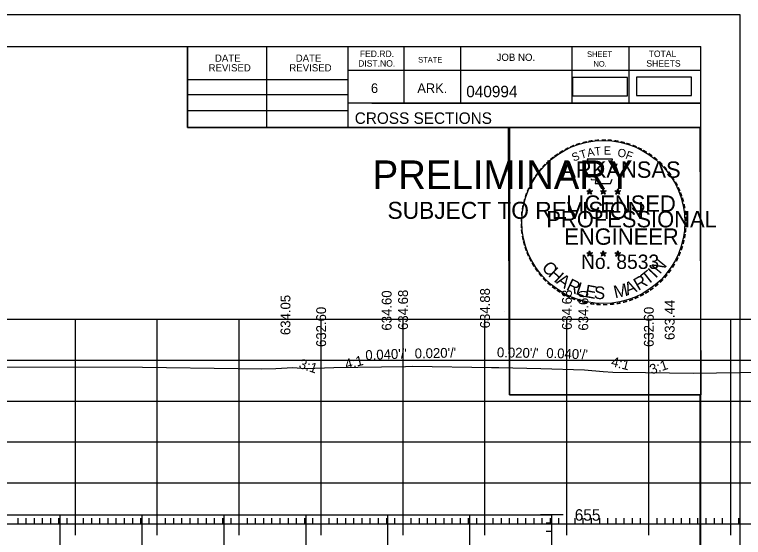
# Model space of a CAD drawing. Extents: x 1381471 to 1382703, y 370300 to 371487.
# Drawn here: x 1382079.2 to 1382168.2, y 371123.8 to 371187.6 of the extents above; entities that cross this region are included whole.
import ezdxf

# ---------------------------------------------------------------- set-up
doc = ezdxf.new("R2010")
doc.units = 0
for name, color, linetype in [('Level 22', 7, 'Continuous'), ('Level 26', 7, 'Continuous'), ('Level 4', 7, 'Continuous'), ('Level 45', 7, 'Continuous'), ('Level 5', 7, 'Continuous'), ('Level 6', 7, 'Continuous'), ('Level 8', 7, 'Continuous'), ('Level 9', 7, 'Continuous')]:
    doc.layers.add(name, color=color, linetype=linetype)

msp = doc.modelspace()

# ---------------------------------------------------------------- linework, layer by layer
at = {"layer": 'Level 22'}
for p, q in [((1381864.772, 371126.544), (1382144.772, 371126.544)), ((1382084.772, 371091.544), (1382084.772, 371126.544)), ((1382094.772, 371091.544), (1382094.772, 371126.544)), ((1382104.772, 371091.544), (1382104.772, 371126.544)), ((1382114.772, 371091.544), (1382114.772, 371126.544)), ((1382124.772, 371091.544), (1382124.772, 371126.544)), ((1382134.772, 371091.544), (1382134.772, 371126.544)), ((1382144.772, 371091.544), (1382144.772, 371126.544))]:
    msp.add_line(p, q, dxfattribs=at)
at = {"layer": 'Level 26'}
for p, q in [((1381834.371, 371187.641), (1382167.705, 371187.641)), ((1382138.986, 371151.411), (1382138.986, 371151.411))]:
    msp.add_line(p, q, dxfattribs=at)
for points in [[(1381834.365, 371187.641), (1382167.705, 371187.641), (1382167.705, 370974.304), (1381834.365, 370974.304)], [(1382080.692, 371183.746), (1382100.312, 371183.746), (1382100.312, 371173.866), (1382116.424, 371173.866), (1382139.624, 371173.866), (1382139.624, 371141.196), (1382162.831, 371141.196), (1382162.952, 370978.286), (1381846.772, 370978.286), (1381846.772, 371183.746)], [(1382139.484, 371173.866), (1382162.831, 371173.866), (1382162.972, 371141.196), (1382139.624, 371141.196)]]:
    msp.add_lwpolyline(points, close=True, dxfattribs=at)
msp.add_circle((1382151.064, 371162.306), 9.952, dxfattribs=at)
at = {"layer": 'Level 4'}
for p, q in [((1382146.172, 371126.544), (1382143.372, 371126.544)), ((1382144.772, 371091.544), (1382144.772, 371126.544)), ((1382144.772, 371125.544), (1382144.072, 371125.544)), ((1382144.772, 371124.544), (1382144.072, 371124.544))]:
    msp.add_line(p, q, dxfattribs=at)
at = {"layer": 'Level 45'}
for p, q in [((1381996.613, 371150.458), (1382276.613, 371150.458)), ((1382086.613, 371125.458), (1382086.613, 371150.458)), ((1382096.613, 371125.458), (1382096.613, 371150.458)), ((1382106.613, 371125.458), (1382106.613, 371150.458)), ((1382116.613, 371125.458), (1382116.613, 371150.458)), ((1382126.613, 371125.458), (1382126.613, 371150.458)), ((1382136.613, 371125.458), (1382136.613, 371150.458)), ((1382146.613, 371125.458), (1382146.613, 371150.458)), ((1382156.613, 371125.458), (1382156.613, 371150.458)), ((1382166.613, 371125.458), (1382166.613, 371150.458)), ((1381996.613, 371145.458), (1382276.613, 371145.458)), ((1381996.613, 371140.458), (1382276.613, 371140.458)), ((1381996.613, 371135.458), (1382276.613, 371135.458)), ((1381996.613, 371130.458), (1382276.613, 371130.458)), ((1382086.613, 371124.058), (1382086.613, 371126.858)), ((1382096.613, 371124.058), (1382096.613, 371126.858)), ((1382106.613, 371124.058), (1382106.613, 371126.858)), ((1382116.613, 371124.058), (1382116.613, 371126.858)), ((1382126.613, 371124.058), (1382126.613, 371126.858)), ((1382136.613, 371124.058), (1382136.613, 371126.858)), ((1382146.613, 371124.058), (1382146.613, 371126.858)), ((1382156.613, 371124.058), (1382156.613, 371126.858)), ((1382166.613, 371124.058), (1382166.613, 371126.858)), ((1381996.613, 371125.458), (1382276.613, 371125.458)), ((1381996.613, 371125.458), (1382276.613, 371125.458)), ((1382079.613, 371125.458), (1382079.613, 371126.158)), ((1382080.613, 371125.458), (1382080.613, 371126.158)), ((1382081.613, 371125.458), (1382081.613, 371126.158)), ((1382082.613, 371125.458), (1382082.613, 371126.158)), ((1382083.613, 371125.458), (1382083.613, 371126.158)), ((1382084.613, 371125.458), (1382084.613, 371126.158)), ((1382085.613, 371125.458), (1382085.613, 371126.158)), ((1382087.613, 371125.458), (1382087.613, 371126.158)), ((1382088.613, 371125.458), (1382088.613, 371126.158)), ((1382089.613, 371125.458), (1382089.613, 371126.158)), ((1382090.613, 371125.458), (1382090.613, 371126.158)), ((1382091.613, 371125.458), (1382091.613, 371126.158)), ((1382092.613, 371125.458), (1382092.613, 371126.158)), ((1382093.613, 371125.458), (1382093.613, 371126.158)), ((1382094.613, 371125.458), (1382094.613, 371126.158)), ((1382095.613, 371125.458), (1382095.613, 371126.158)), ((1382097.613, 371125.458), (1382097.613, 371126.158)), ((1382098.613, 371125.458), (1382098.613, 371126.158)), ((1382099.613, 371125.458), (1382099.613, 371126.158)), ((1382100.613, 371125.458), (1382100.613, 371126.158)), ((1382101.613, 371125.458), (1382101.613, 371126.158)), ((1382102.613, 371125.458), (1382102.613, 371126.158)), ((1382103.613, 371125.458), (1382103.613, 371126.158)), ((1382104.613, 371125.458), (1382104.613, 371126.158)), ((1382105.613, 371125.458), (1382105.613, 371126.158)), ((1382107.613, 371125.458), (1382107.613, 371126.158)), ((1382108.613, 371125.458), (1382108.613, 371126.158)), ((1382109.613, 371125.458), (1382109.613, 371126.158)), ((1382110.613, 371125.458), (1382110.613, 371126.158)), ((1382111.613, 371125.458), (1382111.613, 371126.158)), ((1382112.613, 371125.458), (1382112.613, 371126.158)), ((1382113.613, 371125.458), (1382113.613, 371126.158)), ((1382114.613, 371125.458), (1382114.613, 371126.158)), ((1382115.613, 371125.458), (1382115.613, 371126.158)), ((1382117.613, 371125.458), (1382117.613, 371126.158)), ((1382118.613, 371125.458), (1382118.613, 371126.158)), ((1382119.613, 371125.458), (1382119.613, 371126.158)), ((1382120.613, 371125.458), (1382120.613, 371126.158)), ((1382121.613, 371125.458), (1382121.613, 371126.158)), ((1382122.613, 371125.458), (1382122.613, 371126.158)), ((1382123.613, 371125.458), (1382123.613, 371126.158)), ((1382124.613, 371125.458), (1382124.613, 371126.158)), ((1382125.613, 371125.458), (1382125.613, 371126.158)), ((1382127.613, 371125.458), (1382127.613, 371126.158)), ((1382128.613, 371125.458), (1382128.613, 371126.158)), ((1382129.613, 371125.458), (1382129.613, 371126.158)), ((1382130.613, 371125.458), (1382130.613, 371126.158)), ((1382131.613, 371125.458), (1382131.613, 371126.158)), ((1382132.613, 371125.458), (1382132.613, 371126.158)), ((1382133.613, 371125.458), (1382133.613, 371126.158)), ((1382134.613, 371125.458), (1382134.613, 371126.158)), ((1382135.613, 371125.458), (1382135.613, 371126.158)), ((1382137.613, 371125.458), (1382137.613, 371126.158)), ((1382138.613, 371125.458), (1382138.613, 371126.158)), ((1382139.613, 371125.458), (1382139.613, 371126.158)), ((1382140.613, 371125.458), (1382140.613, 371126.158)), ((1382141.613, 371125.458), (1382141.613, 371126.158)), ((1382142.613, 371125.458), (1382142.613, 371126.158)), ((1382143.613, 371125.458), (1382143.613, 371126.158)), ((1382144.613, 371125.458), (1382144.613, 371126.158)), ((1382145.613, 371125.458), (1382145.613, 371126.158)), ((1382147.613, 371125.458), (1382147.613, 371126.158)), ((1382148.613, 371125.458), (1382148.613, 371126.158)), ((1382149.613, 371125.458), (1382149.613, 371126.158)), ((1382150.613, 371125.458), (1382150.613, 371126.158)), ((1382151.613, 371125.458), (1382151.613, 371126.158)), ((1382152.613, 371125.458), (1382152.613, 371126.158)), ((1382153.613, 371125.458), (1382153.613, 371126.158)), ((1382154.613, 371125.458), (1382154.613, 371126.158)), ((1382155.613, 371125.458), (1382155.613, 371126.158)), ((1382157.613, 371125.458), (1382157.613, 371126.158)), ((1382158.613, 371125.458), (1382158.613, 371126.158)), ((1382159.613, 371125.458), (1382159.613, 371126.158)), ((1382160.613, 371125.458), (1382160.613, 371126.158)), ((1382161.613, 371125.458), (1382161.613, 371126.158)), ((1382162.613, 371125.458), (1382162.613, 371126.158)), ((1382163.613, 371125.458), (1382163.613, 371126.158)), ((1382164.613, 371125.458), (1382164.613, 371126.158)), ((1382165.613, 371125.458), (1382165.613, 371126.158)), ((1382167.613, 371125.458), (1382167.613, 371126.158))]:
    msp.add_line(p, q, dxfattribs=at)
msp.add_lwpolyline([(1382075.859, 371144.641), (1382094.82, 371144.584), (1382097.722, 371144.529), (1382109.377, 371144.395), (1382111.088, 371144.427), (1382113.157, 371144.567), (1382114.7, 371144.426), (1382118.153, 371144.529), (1382126.912, 371144.655), (1382127.752, 371144.716), (1382137.401, 371144.565), (1382138.304, 371144.552), (1382143.434, 371144.41), (1382148.756, 371144.259), (1382151.033, 371144.049), (1382152.228, 371143.96), (1382156.21, 371143.935), (1382162.082, 371143.871), (1382170.525, 371143.981)], dxfattribs=at)
at = {"layer": 'Level 6'}
for p, q in [((1381846.772, 371183.746), (1382162.952, 371183.746)), ((1382100.312, 371173.866), (1382100.312, 371183.746)), ((1382109.992, 371173.866), (1382109.992, 371183.746)), ((1382119.852, 371183.746), (1382119.852, 371173.866)), ((1382126.692, 371183.746), (1382126.692, 371176.806)), ((1382133.632, 371183.746), (1382133.632, 371176.806)), ((1382147.212, 371183.746), (1382147.212, 371176.806)), ((1382154.152, 371183.746), (1382154.152, 371176.806)), ((1382162.952, 370978.286), (1382162.952, 371183.746)), ((1382162.952, 371180.806), (1382119.852, 371180.806)), ((1382162.952, 371180.826), (1382162.952, 371180.826)), ((1382100.312, 371179.726), (1382119.852, 371179.726)), ((1382100.312, 371177.866), (1382119.852, 371177.866)), ((1382162.952, 371176.806), (1382119.852, 371176.806)), ((1382122.812, 371176.806), (1382162.952, 371176.806)), ((1382100.312, 371175.926), (1382119.852, 371175.926)), ((1382162.952, 371173.866), (1382100.312, 371173.866))]:
    msp.add_line(p, q, dxfattribs=at)
for points in [[(1382147.299, 371177.703), (1382154.01, 371177.703), (1382154.01, 371179.94), (1382147.299, 371179.94)], [(1382155.106, 371177.776), (1382161.817, 371177.776), (1382161.817, 371180.013), (1382155.106, 371180.013)]]:
    msp.add_lwpolyline(points, close=True, dxfattribs=at)
at = {"layer": 'Level 8'}
for p, q in [((1382149.386, 371166.376), (1382149.345, 371166.124)), ((1382149.386, 371166.011), (1382149.386, 371166.376)), ((1382149.386, 371166.376), (1382149.435, 371166.126)), ((1382151.056, 371166.376), (1382151.015, 371166.124)), ((1382151.056, 371166.011), (1382151.056, 371166.376)), ((1382151.056, 371166.376), (1382151.105, 371166.126)), ((1382152.82, 371166.364), (1382152.779, 371166.112)), ((1382152.82, 371165.999), (1382152.82, 371166.364)), ((1382152.82, 371166.364), (1382152.869, 371166.114)), ((1382149.037, 371166.122), (1382149.386, 371166.011)), ((1382149.037, 371166.122), (1382149.29, 371166.077)), ((1382149.037, 371166.122), (1382149.274, 371166)), ((1382149.17, 371165.714), (1382149.386, 371166.011)), ((1382149.17, 371165.714), (1382149.296, 371165.958)), ((1382149.17, 371165.714), (1382149.384, 371165.931)), ((1382149.599, 371165.714), (1382149.384, 371165.928)), ((1382149.733, 371166.122), (1382149.386, 371166.011)), ((1382149.599, 371165.714), (1382149.386, 371166.011)), ((1382149.733, 371166.122), (1382149.447, 371166.073)), ((1382149.599, 371165.714), (1382149.462, 371166.005)), ((1382149.733, 371166.122), (1382149.529, 371166.02)), ((1382150.707, 371166.122), (1382151.056, 371166.011)), ((1382150.707, 371166.122), (1382150.96, 371166.077)), ((1382150.707, 371166.122), (1382150.944, 371166)), ((1382150.84, 371165.714), (1382151.056, 371166.011)), ((1382150.84, 371165.714), (1382150.966, 371165.958)), ((1382150.84, 371165.714), (1382151.054, 371165.931)), ((1382151.269, 371165.714), (1382151.054, 371165.928)), ((1382151.403, 371166.122), (1382151.056, 371166.011)), ((1382151.269, 371165.714), (1382151.056, 371166.011)), ((1382151.403, 371166.122), (1382151.117, 371166.073)), ((1382151.269, 371165.714), (1382151.132, 371166.005)), ((1382151.403, 371166.122), (1382151.199, 371166.02)), ((1382152.471, 371166.11), (1382152.82, 371165.999)), ((1382152.471, 371166.11), (1382152.724, 371166.065)), ((1382152.471, 371166.11), (1382152.708, 371165.988)), ((1382152.604, 371165.702), (1382152.82, 371165.999)), ((1382152.604, 371165.702), (1382152.73, 371165.946)), ((1382152.604, 371165.702), (1382152.818, 371165.919)), ((1382153.033, 371165.702), (1382152.818, 371165.916)), ((1382153.167, 371166.11), (1382152.82, 371165.999)), ((1382153.033, 371165.702), (1382152.82, 371165.999)), ((1382153.167, 371166.11), (1382152.881, 371166.061)), ((1382153.033, 371165.702), (1382152.896, 371165.993)), ((1382153.167, 371166.11), (1382152.963, 371166.008)), ((1382149.033, 371158.549), (1382149.382, 371158.438)), ((1382149.033, 371158.549), (1382149.286, 371158.504)), ((1382149.033, 371158.549), (1382149.27, 371158.427)), ((1382149.166, 371158.141), (1382149.382, 371158.438)), ((1382149.166, 371158.141), (1382149.292, 371158.385)), ((1382149.166, 371158.141), (1382149.38, 371158.358)), ((1382149.382, 371158.803), (1382149.341, 371158.551)), ((1382149.595, 371158.141), (1382149.38, 371158.355)), ((1382149.382, 371158.438), (1382149.382, 371158.803)), ((1382149.382, 371158.803), (1382149.431, 371158.553)), ((1382149.729, 371158.549), (1382149.382, 371158.438)), ((1382149.595, 371158.141), (1382149.382, 371158.438)), ((1382149.729, 371158.549), (1382149.443, 371158.5)), ((1382149.595, 371158.141), (1382149.458, 371158.432)), ((1382149.729, 371158.549), (1382149.525, 371158.447)), ((1382150.702, 371158.549), (1382151.051, 371158.438)), ((1382150.702, 371158.549), (1382150.955, 371158.504)), ((1382150.702, 371158.549), (1382150.939, 371158.427)), ((1382150.835, 371158.141), (1382151.051, 371158.438)), ((1382150.835, 371158.141), (1382150.961, 371158.385)), ((1382150.835, 371158.141), (1382151.049, 371158.358)), ((1382151.051, 371158.803), (1382151.01, 371158.551)), ((1382151.264, 371158.141), (1382151.049, 371158.355)), ((1382151.051, 371158.438), (1382151.051, 371158.803)), ((1382151.051, 371158.803), (1382151.1, 371158.553)), ((1382151.398, 371158.549), (1382151.051, 371158.438)), ((1382151.264, 371158.141), (1382151.051, 371158.438)), ((1382151.398, 371158.549), (1382151.112, 371158.5)), ((1382151.264, 371158.141), (1382151.127, 371158.432)), ((1382151.398, 371158.549), (1382151.194, 371158.447)), ((1382152.469, 371158.539), (1382152.818, 371158.428)), ((1382152.469, 371158.539), (1382152.722, 371158.494)), ((1382152.469, 371158.539), (1382152.706, 371158.417)), ((1382152.602, 371158.131), (1382152.818, 371158.428)), ((1382152.602, 371158.131), (1382152.728, 371158.375)), ((1382152.602, 371158.131), (1382152.816, 371158.348)), ((1382152.818, 371158.793), (1382152.777, 371158.541)), ((1382153.031, 371158.131), (1382152.816, 371158.345)), ((1382152.818, 371158.428), (1382152.818, 371158.793)), ((1382152.818, 371158.793), (1382152.867, 371158.543)), ((1382153.165, 371158.539), (1382152.818, 371158.428)), ((1382153.031, 371158.131), (1382152.818, 371158.428)), ((1382153.165, 371158.539), (1382152.879, 371158.49)), ((1382153.031, 371158.131), (1382152.894, 371158.422)), ((1382153.165, 371158.539), (1382152.961, 371158.437))]:
    msp.add_line(p, q, dxfattribs=at)
for points in [[(1382149.078, 371170), (1382149.347, 371169.173)], [(1382152.589, 371169.078), (1382152.731, 371169.362), (1382152.046, 371169.338), (1382152.194, 371170), (1382149.078, 371170)], [(1382149.57, 371167.577), (1382149.57, 371167.49), (1382150.133, 371167.471), (1382150.079, 371166.998), (1382151.949, 371166.998), (1382152.15, 371167.534)], [(1382149.386, 371166.376), (1382149.599, 371165.714), (1382149.037, 371166.122), (1382149.733, 371166.122), (1382149.17, 371165.714), (1382149.386, 371166.376)], [(1382151.056, 371166.376), (1382151.269, 371165.714), (1382150.707, 371166.122), (1382151.403, 371166.122), (1382150.84, 371165.714), (1382151.056, 371166.376)], [(1382152.82, 371166.364), (1382153.033, 371165.702), (1382152.471, 371166.11), (1382153.167, 371166.11), (1382152.604, 371165.702), (1382152.82, 371166.364)], [(1382149.382, 371158.803), (1382149.595, 371158.141), (1382149.033, 371158.549), (1382149.729, 371158.549), (1382149.166, 371158.141), (1382149.382, 371158.803)], [(1382151.051, 371158.803), (1382151.264, 371158.141), (1382150.702, 371158.549), (1382151.398, 371158.549), (1382150.835, 371158.141), (1382151.051, 371158.803)], [(1382152.818, 371158.793), (1382153.031, 371158.131), (1382152.469, 371158.539), (1382153.165, 371158.539), (1382152.602, 371158.131), (1382152.818, 371158.793)]]:
    msp.add_lwpolyline(points, dxfattribs=at)
for centre, radius in [((1382149.385, 371166.01), 0.172), ((1382149.385, 371166.01), 0.145), ((1382149.385, 371166.01), 0.116), ((1382149.385, 371166.01), 0.0991), ((1382149.385, 371166.01), 0.0747), ((1382149.385, 371166.01), 0.0495), ((1382149.385, 371166.01), 0.0296), ((1382151.055, 371166.01), 0.172), ((1382151.055, 371166.01), 0.145), ((1382151.055, 371166.01), 0.116), ((1382151.055, 371166.01), 0.0991), ((1382151.055, 371166.01), 0.0747), ((1382151.055, 371166.01), 0.0495), ((1382151.055, 371166.01), 0.0296), ((1382152.819, 371165.998), 0.172), ((1382152.819, 371165.998), 0.145), ((1382152.819, 371165.998), 0.116), ((1382152.819, 371165.998), 0.0991), ((1382152.819, 371165.998), 0.0747), ((1382152.819, 371165.998), 0.0495), ((1382152.819, 371165.998), 0.0296), ((1382149.381, 371158.437), 0.172), ((1382149.381, 371158.437), 0.145), ((1382149.381, 371158.437), 0.116), ((1382149.381, 371158.437), 0.0991), ((1382149.381, 371158.437), 0.0747), ((1382149.381, 371158.437), 0.0495), ((1382149.381, 371158.437), 0.0296), ((1382151.05, 371158.437), 0.172), ((1382151.05, 371158.437), 0.145), ((1382151.05, 371158.437), 0.116), ((1382151.05, 371158.437), 0.0991), ((1382151.05, 371158.437), 0.0747), ((1382151.05, 371158.437), 0.0495), ((1382151.05, 371158.437), 0.0296), ((1382152.817, 371158.427), 0.172), ((1382152.817, 371158.427), 0.145), ((1382152.817, 371158.427), 0.116), ((1382152.817, 371158.427), 0.0991), ((1382152.817, 371158.427), 0.0747), ((1382152.817, 371158.427), 0.0495), ((1382152.817, 371158.427), 0.0296)]:
    msp.add_circle(centre, radius, dxfattribs=at)

# ---------------------------------------------------------------- texts
at = {"layer": 'Level 45'}
for s, rotation, p in [('634.60', 90, (1382125.213, 371149.055)), ('634.68', 90, (1382127.213, 371149.135)), ('634.88', 90, (1382137.213, 371149.335)), ('634.68', 90, (1382147.213, 371149.135)), ('634.60', 90, (1382149.213, 371149.055)), ('634.05', 90, (1382112.861, 371148.506)), ('633.44', 90, (1382159.757, 371147.903)), ('632.60', 90, (1382117.213, 371147.055)), ('632.60', 90, (1382157.213, 371147.055)), ("0.040'/'", 2.29061, (1382122.034, 371145.452)), ("0.020'/'", 1.14576, (1382128.042, 371145.664)), ("0.020'/'", 358.85424, (1382138.062, 371145.806)), ("0.040'/'", 357.70939, (1382144.074, 371145.737)), ('4:1', 14.03624, (1382119.685, 371144.339)), ('3:1', 341.56522, (1382113.806, 371144.518)), ('4:1', 345.96376, (1382151.928, 371144.742)), ('3:1', 18.43493, (1382156.938, 371143.69))]:
    msp.add_text(s, height=1.2, rotation=rotation, dxfattribs=at).set_placement(p)
at = {"layer": 'Level 5'}
msp.add_text('655', height=1.4, dxfattribs=at).set_placement((1382147.572, 371125.844))
at = {"layer": 'Level 6'}
for s, height, p in [('FED.RD.', 0.7819, (1382121.332, 371182.466)), ('TOTAL', 0.7819, (1382156.592, 371182.466)), ('DATE', 0.8792, (1382103.65, 371181.883)), ('DATE', 0.8792, (1382113.51, 371181.883)), ('STATE', 0.684, (1382128.452, 371181.786)), ('JOB NO.', 0.8792, (1382138.032, 371181.986)), ('SHEET', 0.684, (1382149.072, 371182.466)), ('REVISED', 0.8792, (1382102.87, 371180.703)), ('REVISED', 0.8792, (1382112.73, 371180.703)), ('DIST.NO.', 0.7819, (1382121.132, 371181.286)), ('NO.', 0.684, (1382149.852, 371181.286)), ('SHEETS', 0.7819, (1382156.312, 371181.286)), ('6', 1.172, (1382122.692, 371178.066)), ('ARK.', 1.1723, (1382128.352, 371178.066)), ('040994', 1.4, (1382134.328, 371177.546)), ('CROSS SECTIONS', 1.4, (1382120.716, 371174.297))]:
    msp.add_text(s, height=height, rotation=360, dxfattribs=at).set_placement(p)
at = {"layer": 'Level 8'}
for s, height, rotation, p in [('-', 1.6, 24.30721, (1382147.192, 371170.858)), ('-', 1.6, 19.17608, (1382147.826, 371171.127)), ('-', 1.6, 13.63015, (1382148.576, 371171.368)), ('-', 1.6, 10.21935, (1382149.254, 371171.53)), ('-', 1.6, 5.89682, (1382149.983, 371171.64)), ('-', 1.6, 0.18623, (1382150.755, 371171.712)), ('-', 1.6, 357.74304, (1382151.478, 371171.699)), ('-', 1.6, 352.16172, (1382152.222, 371171.643)), ('-', 1.6, 347.20489, (1382152.941, 371171.529)), ('-', 1.6, 342.3362, (1382153.576, 371171.374)), ('-', 1.6, 337.85509, (1382154.311, 371171.151)), ('-', 1.6, 34.06357, (1382145.962, 371170.171)), ('-', 1.6, 28.79182, (1382146.559, 371170.541)), ('S', 1, 21.59401, (1382147.433, 371169.678)), ('T', 1, 16.4036, (1382148.347, 371170.009)), ('A', 1, 11.21318, (1382149.173, 371170.26)), ('T', 1, 6.02276, (1382150.022, 371170.426)), ('E', 1, 0.83234, (1382151.127, 371170.536)), ('O', 1, 350.4515, (1382152.731, 371170.326)), ('F', 1, 340.07066, (1382153.685, 371170.098)), ('-', 1.6, 334.12109, (1382154.942, 371170.88)), ('-', 1.6, 329.64089, (1382155.521, 371170.597)), ('-', 1.6, 42.96224, (1382144.475, 371168.981)), ('-', 1.6, 38.95066, (1382144.908, 371169.398)), ('-', 1.6, 36.23174, (1382145.384, 371169.776)), ('-', 1.6, 325.86266, (1382156.164, 371170.236)), ('-', 1.6, 320.52971, (1382156.774, 371169.81)), ('-', 1.6, 48.42305, (1382144.027, 371168.503)), ('ARKANSAS', 2, 360, (1382145.931, 371167.712)), ('-', 1.6, 315.57859, (1382157.373, 371169.322)), ('-', 1.6, 309.87973, (1382157.942, 371168.772)), ('-', 1.6, 54.23247, (1382143.211, 371167.45)), ('-', 1.6, 50.61417, (1382143.624, 371168.017)), ('-', 1.6, 306.65218, (1382158.467, 371168.17)), ('-', 1.6, 58.07063, (1382142.886, 371166.923)), ('-', 1.4, 303.67529, (1382158.953, 371167.602)), ('-', 1.6, 299.66835, (1382159.272, 371166.995)), ('-', 1.6, 67.77427, (1382142.314, 371165.698)), ('-', 1.6, 62.87135, (1382142.573, 371166.309)), ('-', 1.6, 294.66279, (1382159.596, 371166.383)), ('-', 1.6, 72.39447, (1382142.095, 371165.068)), ('LICENSED', 2, 360, (1382146.528, 371163.563)), ('DWB', 0.01, 360, (1382149.373, 371166.005)), ('DWB', 0.01, 360, (1382151.043, 371166.005)), ('DWB', 0.01, 360, (1382152.807, 371165.995)), ('-', 1.6, 290.57283, (1382159.853, 371165.806)), ('-', 1.6, 75.46096, (1382141.898, 371164.354)), ('-', 1.6, 285.12326, (1382160.087, 371165.226)), ('-', 1.6, 81.20126, (1382141.766, 371163.641)), ('PROFESSIONAL', 2, 360, (1382144.105, 371161.659)), ('-', 1.6, 280.54934, (1382160.287, 371164.484)), ('-', 1.6, 276.59616, (1382160.449, 371163.716)), ('-', 1.6, 89.06224, (1382141.665, 371162.249)), ('-', 1.6, 85.18634, (1382141.69, 371162.95)), ('-', 1.6, 274.33011, (1382160.509, 371162.994)), ('-', 1.6, 94.19588, (1382141.7, 371161.524)), ('-', 1.6, 269.94067, (1382160.543, 371162.362)), ('-', 1.6, 98.94793, (1382141.772, 371160.857)), ('ENGINEER', 2, 360, (1382146.292, 371159.534)), ('-', 1.6, 263.5172, (1382160.524, 371161.696)), ('-', 1.6, 101.71495, (1382141.907, 371160.124)), ('-', 1.6, 255.7626, (1382160.343, 371160.364)), ('-', 1.6, 260.99529, (1382160.453, 371161.042)), ('-', 1.6, 105.45785, (1382142.069, 371159.529)), ('-', 1.6, 109.08742, (1382142.284, 371158.898)), ('-', 1.6, 252.86809, (1382160.162, 371159.644)), ('-', 1.6, 114.06432, (1382142.538, 371158.302)), ('No. 8533', 1.757, 360, (1382148.334, 371156.583)), ('DWB', 0.01, 360, (1382149.369, 371158.433)), ('DWB', 0.01, 360, (1382151.038, 371158.433)), ('DWB', 0.01, 360, (1382152.805, 371158.423)), ('-', 1.6, 247.88866, (1382159.939, 371158.971)), ('-', 1.6, 115.72885, (1382142.843, 371157.684)), ('N', 1.54, 50.78344, (1382157.971, 371155.882)), ('-', 1.6, 244.61971, (1382159.677, 371158.342)), ('-', 1.6, 120.44712, (1382143.2, 371157.098)), ('-', 1.6, 125.89344, (1382143.603, 371156.537)), ('C', 1.54, 309.95483, (1382143.456, 371156.729)), ('H', 1.54, 317.38726, (1382144.242, 371155.792)), ('I', 1.54, 46.30332, (1382157.448, 371155.362)), ('-', 1.6, 233.84524, (1382158.881, 371156.937)), ('-', 1.6, 239.07125, (1382159.283, 371157.59)), ('-', 1.6, 130.71812, (1382144.065, 371155.985)), ('A', 1.54, 325.55777, (1382145.237, 371154.888)), ('R', 1.54, 30.55277, (1382155.324, 371153.89)), ('T', 1.54, 38.42805, (1382156.437, 371154.553)), ('-', 1.6, 231.25377, (1382158.451, 371156.371)), ('-', 1.6, 134.22381, (1382144.582, 371155.44)), ('-', 1.6, 138.93382, (1382145.107, 371154.976)), ('R', 1.54, 334.31873, (1382146.435, 371154.087)), ('L', 1.54, 342.19401, (1382147.604, 371153.531)), ('M', 1.54, 12.44038, (1382152.496, 371152.982)), ('A', 1.54, 21.7918, (1382153.992, 371153.339)), ('-', 1.6, 221.08509, (1382157.45, 371155.298)), ('-', 1.6, 225.76533, (1382157.972, 371155.807)), ('-', 1.6, 144.64634, (1382145.663, 371154.57)), ('-', 1.6, 148.08978, (1382146.224, 371154.199)), ('E', 1.54, 349.33121, (1382148.722, 371153.169)), ('S', 1.54, 356.46841, (1382149.875, 371152.948)), ('-', 1.6, 212.24909, (1382156.367, 371154.439)), ('-', 1.6, 215.73633, (1382156.901, 371154.826)), ('-', 1.6, 151.57039, (1382146.803, 371153.874)), ('-', 1.6, 154.60019, (1382147.325, 371153.627)), ('-', 1.6, 158.56121, (1382147.949, 371153.373)), ('-', 1.6, 204.25161, (1382155.185, 371153.774)), ('-', 1.6, 207.35684, (1382155.809, 371154.093)), ('-', 1.6, 162.79826, (1382148.636, 371153.16)), ('-', 1.6, 167.55551, (1382149.351, 371152.996)), ('-', 1.6, 173.11546, (1382150.123, 371152.886)), ('-', 1.6, 176.51827, (1382150.871, 371152.833)), ('-', 1.6, 181.59176, (1382151.615, 371152.852)), ('-', 1.6, 185.81666, (1382152.424, 371152.928)), ('-', 1.6, 191.28576, (1382153.16, 371153.06)), ('-', 1.6, 195.47429, (1382153.889, 371153.259)), ('-', 1.6, 200.71842, (1382154.566, 371153.501))]:
    msp.add_text(s, height=height, rotation=rotation, dxfattribs=at).set_placement(p)
at = {"layer": 'Level 9'}
for s, height, p in [('PRELIMINARY', 3.5, (1382122.903, 371166.33)), ('DWB', 0.01, (1382123.65, 371168.179)), ('SUBJECT TO REVISION', 2.07511, (1382124.712, 371162.701))]:
    msp.add_text(s, height=height, rotation=360, dxfattribs=at).set_placement(p)

doc.saveas('drawing.dxf')
